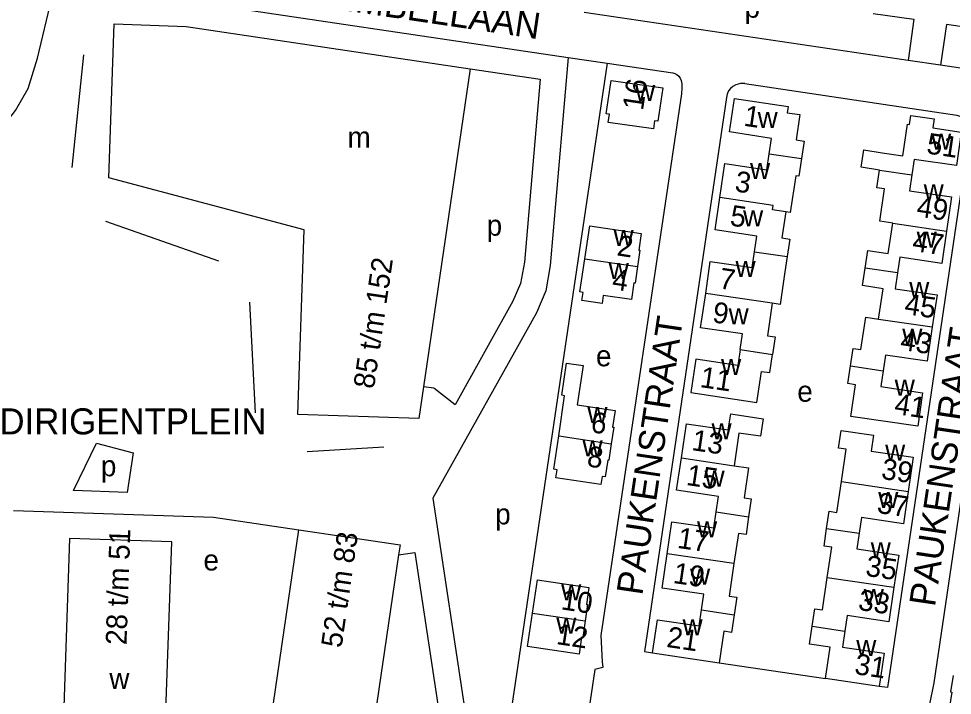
# Model space of a CAD drawing. Extents: x 163012 to 165277, y 382513 to 383987.
# Drawn here: x 164286.1 to 164465.3, y 383079.5 to 383209.4 of the extents above; entities that cross this region are included whole.
import ezdxf

# ---------------------------------------------------------------- set-up
doc = ezdxf.new("R2010")
doc.units = 0
for name, color, linetype in [('BLT_Basislijn', 7, 'Continuous'), ('BLT_Bebouwing', 7, 'Continuous'), ('BLT_Centroide', 7, 'Continuous'), ('BLT_Huisnummer', 7, 'Continuous'), ('BLT_Huisnummer_reeks', 7, 'Continuous'), ('BLT_Onderverdeling_panden', 7, 'Continuous'), ('BLT_Straatnaam', 7, 'Continuous')]:
    doc.layers.add(name, color=color, linetype=linetype)

msp = doc.modelspace()

# ---------------------------------------------------------------- linework, layer by layer
at = {"layer": 'BLT_Basislijn'}
for p, q in [((164307.28, 383214.49), (164391.56, 383201.97)), ((164456.85, 383201.38), (164394.65, 383210.59)), ((164298.57, 383202.49), (164296.33, 383180.83)), ((164391.56, 383201.97), (164399.04, 383200.86)), ((164399.04, 383200.86), (164378.38, 383061.27)), ((164399.04, 383200.86), (164411.69, 383198.98)), ((164463.09, 383200.45), (164456.85, 383201.38)), ((164525.44, 383191.22), (164463.09, 383200.45)), ((164425.47, 383196.94), (164466.17, 383190.89)), ((164302.77, 383170.53), (164324.47, 383162.91)), ((164330.41, 383155.01), (164331.47, 383133.72)), ((164341.47, 383126.32), (164356.22, 383127.21)), ((164365.6, 383117.39), (164375.5, 383052.06)), ((164420.58, 383085.79), (164440.97, 383082.76))]:
    msp.add_line(p, q, dxfattribs=at)
for points in [[(164269.92, 383176.86), (164270.61, 383178.43), (164275.99, 383182.3), (164282.49, 383187.94), (164285.5, 383191.75), (164287.9, 383196.02), (164289.7, 383201.81), (164292.48, 383213.42)], [(164450.16, 383210.41), (164457.97, 383209.28), (164456.85, 383201.38)], [(164472.16, 383207.13), (164464.22, 383208.31), (164463.09, 383200.45)], [(164391.56, 383201.97), (164388.15, 383162.03), (164387.28, 383157.14), (164385.48, 383152.97), (164365.6, 383117.39)], [(164372.79, 383199.8), (164386.18, 383197.81), (164383.19, 383162.68), (164382.46, 383158.59), (164380.99, 383155.18), (164369.87, 383135.29), (164365.77, 383138.46), (164363.8, 383138.71)], [(164411.69, 383198.98), (164412.05, 383198.86), (164412.43, 383198.68), (164412.81, 383198.36), (164413.09, 383197.98), (164413.26, 383197.52), (164413.39, 383196.9), (164413.43, 383196.13), (164413.32, 383194.98), (164397.86, 383091), (164398.09, 383085.94), (164398.23, 383084.84), (164396.72, 383084.46), (164392.94, 383059.13)], [(164425.47, 383196.94), (164424.69, 383196.93), (164424.21, 383196.85), (164423.74, 383196.69), (164423.22, 383196.39), (164422.74, 383195.97), (164422.39, 383195.53), (164422.1, 383194.93), (164421.95, 383194.29), (164406.21, 383087.91), (164407.8, 383087.68)], [(164466.17, 383190.89), (164466.95, 383190.64), (164467.49, 383190.29), (164467.95, 383189.84), (164468.29, 383189.35), (164468.53, 383188.8), (164468.65, 383188.12), (164468.61, 383187.39), (164452.91, 383081), (164451.31, 383081.24)], [(164480.56, 383188.75), (164479.75, 383188.76), (164479.26, 383188.66), (164478.69, 383188.34), (164478.17, 383187.84), (164477.65, 383186.95), (164477.28, 383185.55), (164476, 383178.07), (164461.8, 383081.93), (164460.94, 383077.84), (164460.05, 383075.97), (164461.02, 383075.51), (164457.3, 383049.57)], [(164285.13, 383115.03), (164323.49, 383113.71), (164339.9, 383111.29)], [(164359.03, 383106.48), (164362.13, 383106.93), (164370.33, 383052.83)]]:
    msp.add_lwpolyline(points, dxfattribs=at)
msp.add_lwpolyline([(164296.64, 383118.84), (164301.06, 383127.94), (164308.08, 383126.09), (164306.95, 383118.43)], close=True, dxfattribs=at)
at = {"layer": 'BLT_Bebouwing'}
for p, q in [((164333.52, 383067.87), (164339.9, 383111.29)), ((164407.8, 383087.68), (164420.58, 383085.79)), ((164451.31, 383081.24), (164440.97, 383082.76))]:
    msp.add_line(p, q, dxfattribs=at)
for points in [[(164363.8, 383138.71), (164362.9, 383132.65), (164339.66, 383133.43), (164340.88, 383168.87), (164303.41, 383178.84), (164304.42, 383208.39), (164318.25, 383207.92), (164372.79, 383199.8)], [(164372.79, 383199.8), (164363.8, 383138.71)], [(164430.15, 383183.47), (164430.59, 383186.43), (164422.57, 383187.67), (164423.5, 383194.06), (164433.82, 383192.53), (164433.65, 383191.34), (164436.05, 383190.98), (164435.33, 383186.14), (164436.89, 383185.9), (164436.4, 383182.55)], [(164451.36, 383180.33), (164447.84, 383180.87), (164448.33, 383184.2), (164451.86, 383183.68), (164455.81, 383183.1), (164456.7, 383189.16), (164457.08, 383189.1), (164457.34, 383190.84), (164461.85, 383190.17), (164461.58, 383188.43), (164467.04, 383187.62), (164466.1, 383181.2), (164458, 383182.36), (164457.57, 383179.41)], [(164420.68, 383175.06), (164421.65, 383181.59), (164429.7, 383180.41), (164430.15, 383183.47)], [(164436.4, 383182.55), (164435.89, 383179.15), (164435.26, 383179.24), (164434.21, 383172.23), (164433.37, 383172.35)], [(164453.9, 383170.14), (164451.41, 383170.51), (164452.34, 383176.74), (164450.86, 383176.96), (164451.36, 383180.33)], [(164457.57, 383179.41), (164457.13, 383176.35), (164465.17, 383175.18), (164464.22, 383168.62)], [(164427.34, 383164.68), (164427.78, 383167.68), (164419.78, 383168.87), (164420.68, 383175.06)], [(164433.37, 383172.35), (164432.63, 383167.31), (164434.11, 383167.11), (164433.61, 383163.75)], [(164394.79, 383163.33), (164395.72, 383169.66), (164405.62, 383168.2), (164405.15, 383164.99), (164405.37, 383164.96), (164404.9, 383161.84)], [(164448.58, 383161.54), (164449.08, 383164.89), (164453.04, 383164.32), (164453.9, 383170.14)], [(164464.22, 383168.62), (164463.32, 383162.42), (164455.26, 383163.63), (164454.81, 383160.61)], [(164417.98, 383156.67), (164418.87, 383162.81), (164426.9, 383161.64), (164427.34, 383164.68)], [(164404.9, 383161.84), (164404.42, 383158.66), (164404.21, 383158.69), (164403.75, 383155.48), (164398.33, 383156.27), (164398.11, 383154.72), (164394.22, 383155.28), (164394.45, 383156.85), (164393.85, 383156.95), (164394.79, 383163.33)], [(164433.61, 383163.75), (164433.12, 383160.38), (164432.25, 383154.56), (164430.76, 383154.78)], [(164451.17, 383151.75), (164452.03, 383157.57), (164448.07, 383158.16), (164448.58, 383161.54)], [(164454.81, 383160.61), (164454.36, 383157.58), (164462.41, 383156.38), (164461.49, 383150.23)], [(164424.58, 383145.88), (164425.03, 383148.88), (164417, 383150.08), (164417.98, 383156.67)], [(164430.76, 383154.78), (164429.83, 383148.55), (164431.32, 383148.31), (164430.83, 383144.95)], [(164445.79, 383142.74), (164446.29, 383146.1), (164447.77, 383145.88), (164448.7, 383152.12), (164451.17, 383151.75)], [(164461.49, 383150.23), (164460.52, 383143.64), (164452.47, 383144.81), (164452.03, 383141.82)], [(164424.58, 383145.88), (164424.13, 383142.85), (164416.11, 383144.04), (164415.16, 383137.63), (164427.82, 383135.74), (164428.72, 383141.7), (164430.32, 383141.46), (164430.83, 383144.95)], [(164389.77, 383129.32), (164390.91, 383137.03), (164390.36, 383137.11), (164391.27, 383143.3), (164394.45, 383142.83), (164393.34, 383135.29), (164400.59, 383134.22), (164400.12, 383131), (164400.32, 383130.97), (164399.86, 383127.83)], [(164452.03, 383141.82), (164451.59, 383138.79), (164459.63, 383137.59), (164458.69, 383131.18), (164445.85, 383133.07), (164446.76, 383139.15), (164445.28, 383139.38), (164445.79, 383142.74)], [(164413.31, 383125.1), (164414.27, 383131.63), (164422.32, 383130.48), (164422.79, 383133.55), (164429, 383132.61), (164428.51, 383129.26), (164424.33, 383129.87), (164423.42, 383123.6)], [(164444.04, 383120.55), (164444.97, 383126.8), (164443.48, 383126.97), (164444, 383130.38), (164450.22, 383129.47), (164449.77, 383126.42), (164457.8, 383125.24), (164456.84, 383118.66)], [(164399.86, 383127.83), (164399.39, 383124.66), (164399.2, 383124.68), (164398.71, 383121.48), (164398.1, 383121.56), (164397.86, 383119.99), (164389.21, 383121.25), (164389.45, 383122.82), (164388.82, 383122.93), (164389.77, 383129.32)], [(164419.99, 383114.72), (164420.43, 383117.7), (164412.39, 383118.92), (164413.31, 383125.1)], [(164423.42, 383123.6), (164426.18, 383123.2), (164425.34, 383117.43), (164426.73, 383117.23), (164426.23, 383113.79)], [(164441.2, 383111.58), (164441.67, 383114.86), (164443.16, 383114.64), (164444.04, 383120.55)], [(164456.84, 383118.66), (164455.93, 383112.47), (164447.9, 383113.67), (164447.45, 383110.65)], [(164410.61, 383106.71), (164411.51, 383112.85), (164419.54, 383111.67), (164419.99, 383114.72)], [(164426.23, 383113.79), (164425.73, 383110.38), (164424.26, 383110.61), (164423.4, 383104.82)], [(164339.9, 383111.29), (164359.31, 383108.41), (164359.03, 383106.48)], [(164441.32, 383102.16), (164442.18, 383107.96), (164440.7, 383108.18), (164441.2, 383111.58)], [(164447.45, 383110.65), (164447, 383107.64), (164455.04, 383106.44), (164454.12, 383100.27)], [(164417.2, 383095.92), (164417.64, 383098.93), (164409.63, 383100.12), (164410.61, 383106.71)], [(164359.03, 383106.48), (164352.92, 383064.99)], [(164423.4, 383104.82), (164422.46, 383098.59), (164423.96, 383098.37), (164423.46, 383095)], [(164384.74, 383095.31), (164385.68, 383101.67), (164395.56, 383100.24), (164395.09, 383096.98), (164395.31, 383096.95), (164394.84, 383093.82)], [(164438.42, 383092.78), (164438.91, 383096.12), (164440.39, 383095.91), (164441.32, 383102.16)], [(164454.12, 383100.27), (164453.14, 383093.66), (164445.12, 383094.82), (164444.68, 383091.86)], [(164407.8, 383087.68), (164408.72, 383094.05), (164416.75, 383092.88), (164417.2, 383095.92)], [(164394.84, 383093.82), (164394.37, 383090.64), (164394.15, 383090.66), (164393.69, 383087.46), (164383.79, 383088.92), (164384.74, 383095.31)], [(164423.46, 383095), (164422.95, 383091.6), (164421.47, 383091.82), (164420.58, 383085.79)], [(164440.97, 383082.76), (164441.86, 383088.8), (164437.93, 383089.38), (164438.42, 383092.78)], [(164444.68, 383091.86), (164444.22, 383088.8), (164452.26, 383087.6), (164451.31, 383081.24)], [(164465.48, 383083.36), (164465.01, 383080.18), (164465.23, 383080.14), (164464.75, 383076.94), (164464.67, 383076.39), (164464.97, 383076.35), (164464.65, 383074.2), (164469.18, 383073.53), (164469.49, 383075.68), (164474.55, 383074.93), (164474.63, 383075.48), (164475.57, 383081.87)]]:
    msp.add_lwpolyline(points, dxfattribs=at)
for points in [[(164399.84, 383197.54), (164409.73, 383196.1), (164408.79, 383189.71), (164408.17, 383189.79), (164407.95, 383188.28), (164399.29, 383189.49), (164399.51, 383191.06), (164398.9, 383191.16)], [(164295.86, 383109.65), (164294.7, 383075.42), (164314.31, 383074.74), (164315.51, 383108.98)]]:
    msp.add_lwpolyline(points, close=True, dxfattribs=at)
at = {"layer": 'BLT_Onderverdeling_panden'}
for p, q in [((164430.15, 383183.47), (164436.4, 383182.55)), ((164451.36, 383180.33), (164457.57, 383179.41)), ((164453.9, 383170.14), (164464.22, 383168.62)), ((164427.34, 383164.68), (164433.61, 383163.75)), ((164394.79, 383163.33), (164404.9, 383161.84)), ((164454.81, 383160.61), (164448.58, 383161.54)), ((164430.76, 383154.78), (164417.98, 383156.67)), ((164451.17, 383151.75), (164461.49, 383150.23)), ((164424.58, 383145.88), (164430.83, 383144.95)), ((164445.79, 383142.74), (164452.03, 383141.82)), ((164389.77, 383129.32), (164399.86, 383127.83)), ((164413.31, 383125.1), (164423.42, 383123.6)), ((164444.04, 383120.55), (164456.84, 383118.66)), ((164419.99, 383114.72), (164426.23, 383113.79)), ((164441.2, 383111.58), (164447.45, 383110.65)), ((164423.4, 383104.82), (164410.61, 383106.71)), ((164441.32, 383102.16), (164454.12, 383100.27)), ((164417.2, 383095.92), (164423.46, 383095)), ((164384.74, 383095.31), (164394.84, 383093.82)), ((164438.42, 383092.78), (164444.68, 383091.86))]:
    msp.add_line(p, q, dxfattribs=at)
msp.add_lwpolyline([(164433.37, 383172.35), (164430.82, 383172.73), (164430.94, 383173.54), (164420.68, 383175.06)], dxfattribs=at)

# ---------------------------------------------------------------- texts
at = {"layer": 'BLT_Centroide'}
for s, p in [('p', (164425.45, 383209.58)), ('w', (164404.43, 383193.62)), ('w', (164427.95, 383188.44)), ('m', (164349.23, 383184.66)), ('w', (164461.26, 383184.28)), ('w', (164426.49, 383178.62)), ('w', (164459.82, 383174.56)), ('w', (164425.16, 383169.53)), ('p', (164375.94, 383167.74)), ('w', (164400.3, 383165.78)), ('w', (164458.48, 383165.47)), ('w', (164399.37, 383159.41)), ('w', (164423.71, 383159.81)), ('w', (164457.05, 383155.81)), ('w', (164422.38, 383150.75)), ('w', (164455.72, 383146.81)), ('e', (164396.92, 383142.68)), ('w', (164420.93, 383141)), ('e', (164435.56, 383135.88)), ('w', (164454.27, 383137.03)), ('w', (164395.27, 383131.78)), ('w', (164419.1, 383128.66)), ('w', (164394.34, 383125.38)), ('w', (164452.43, 383124.59)), ('p', (164301.88, 383121.57)), ('w', (164417.76, 383119.59)), ('w', (164451.09, 383115.5)), ('p', (164377.57, 383112.33)), ('w', (164416.32, 383109.84)), ('w', (164449.66, 383105.84)), ('e', (164321.57, 383103.49)), ('w', (164414.98, 383100.78)), ('w', (164390.24, 383097.75)), ('w', (164448.32, 383096.84)), ('w', (164389.3, 383091.38)), ('w', (164413.54, 383091.06)), ('w', (164446.88, 383087.09)), ('w', (164303.5, 383080.77))]:
    msp.add_text(s, height=4, dxfattribs=at).set_placement(p)
at = {"layer": 'BLT_Huisnummer'}
for s, rotation, p in [('16', 81.5826, (164405.94, 383191.66)), ('1', 351.5824, (164425.14, 383188.87)), ('51', 351.5824, (164460.23, 383183.55)), ('3', 351.5824, (164423.42, 383176.27)), ('49', 351.5824, (164458.31, 383171.47)), ('5', 351.5824, (164422.49, 383169.72)), ('2', 351.5826, (164400.8, 383163.98)), ('47', 351.5824, (164457.49, 383164.86)), ('4', 351.5826, (164399.87, 383157.49)), ('7', 351.5824, (164420.39, 383157.66)), ('9', 351.5824, (164419.13, 383151.15)), ('45', 351.5824, (164455.98, 383152.73)), ('43', 351.5824, (164455.18, 383145.87)), ('11', 351.5824, (164416.75, 383138.71)), ('41', 351.5824, (164454.05, 383133.55)), ('6', 351.5826, (164395.76, 383130.05)), ('13', 351.5824, (164415.16, 383126.61)), ('8', 351.5826, (164395.04, 383123.5)), ('39', 351.5824, (164451.53, 383121.1)), ('15', 351.5824, (164414.11, 383119.92)), ('37', 351.5824, (164450.72, 383114.57)), ('17', 351.5824, (164412.39, 383107.85)), ('19', 351.5824, (164411.58, 383101.11)), ('35', 351.5824, (164448.51, 383102.49)), ('10', 351.5826, (164390.07, 383096.05)), ('33', 351.5824, (164447.1, 383095.95)), ('12', 351.5826, (164389.16, 383089.38)), ('21', 351.5824, (164410.33, 383088.83)), ('31', 351.5824, (164446.39, 383083.63))]:
    msp.add_text(s, height=4, rotation=rotation, dxfattribs=at).set_placement(p)
at = {"layer": 'BLT_Huisnummer_reeks'}
for s, rotation, p in [('85 t/m 152', 81.6273, (164354.29, 383138.23)), ('28 t/m 51', 88.0462, (164306.79, 383089.14)), ('52 t/m 83', 81.8339, (164348.08, 383088.52))]:
    msp.add_text(s, height=4, rotation=rotation, dxfattribs=at).set_placement(p)
at = {"layer": 'BLT_Straatnaam'}
for s, rotation, p in [('KLAVECIMBELLAAN', 351.5769, (164322.62, 383214.82)), ('PAUKENSTRAAT', 81.6098, (164405.8, 383098.58)), ('PAUKENSTRAAT', 81.6098, (164461.98, 383096.39))]:
    msp.add_text(s, height=5, rotation=rotation, dxfattribs=at).set_placement(p)
msp.add_text('DIRIGENTPLEIN', height=5, dxfattribs=at).set_placement((164282.4, 383129.61))

doc.saveas('drawing.dxf')
